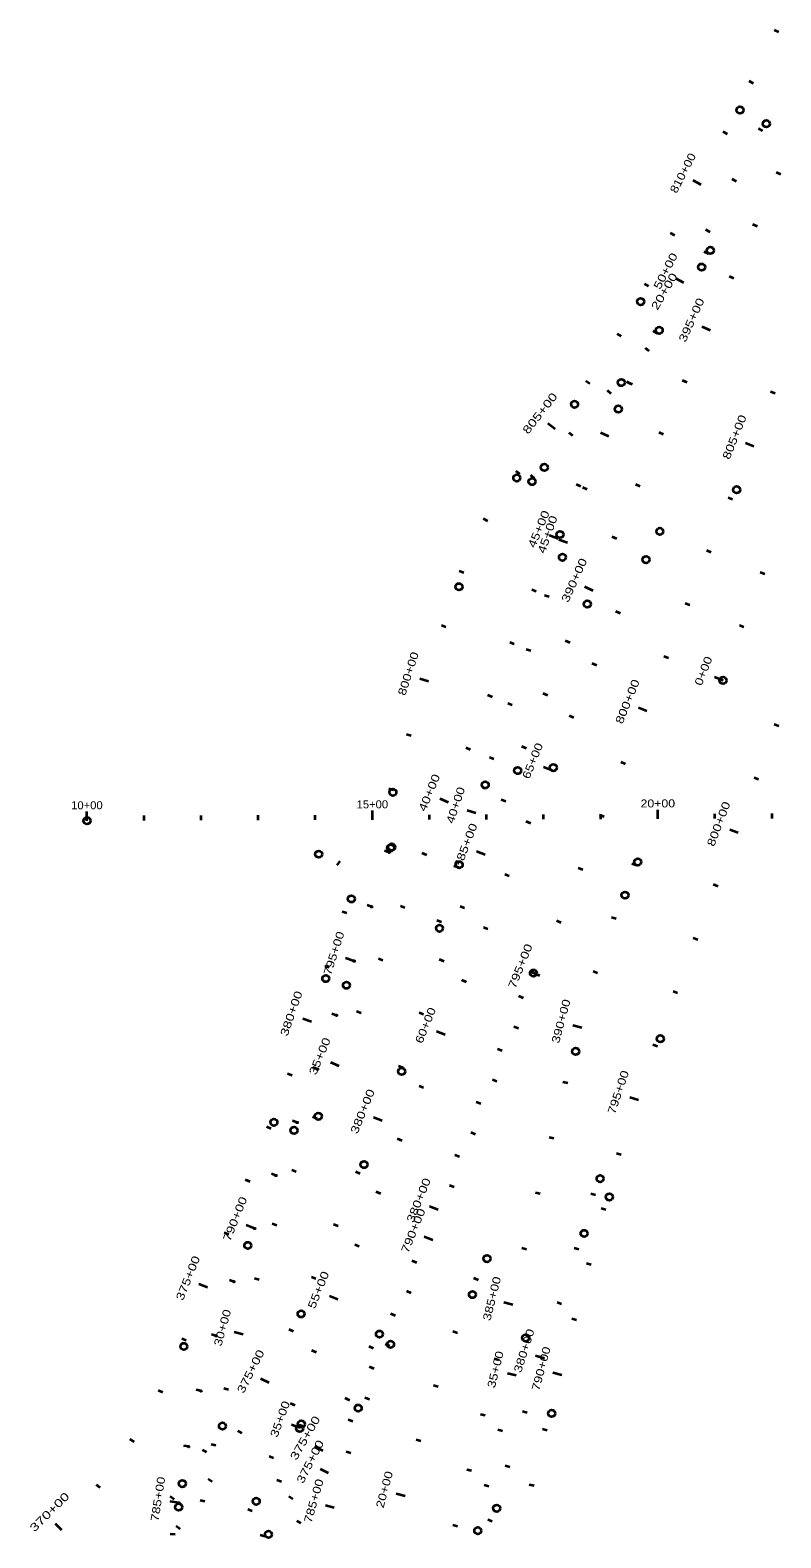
# Model space of a CAD drawing. Extents: x 2357892 to 2370172, y 6966790 to 6985499.
# Drawn here: x 2364077 to 2365392, y 6979263 to 6981905 of the extents above; entities that cross this region are included whole.
import ezdxf
from ezdxf.enums import TextEntityAlignment as Align

# ---------------------------------------------------------------- set-up
doc = ezdxf.new("R2010")
doc.units = 0
doc.header["$LTSCALE"] = 5.6
doc.header["$PDMODE"] = 32
doc.header["$PDSIZE"] = 2.8
doc.layers.add('28', color=7, linetype='Continuous', lineweight=35)
doc.layers.add('7', color=7, linetype='Continuous')

msp = doc.modelspace()

# ---------------------------------------------------------------- linework, layer by layer
at = {"layer": '28'}
for p, q in [((2365389.008, 6981900.982), (2365381.359, 6981904.69)), ((2365344.597, 6981811.386), (2365337.015, 6981815.228)), ((2365298.789, 6981722.496), (2365291.243, 6981726.408)), ((2365360.417, 6981728.387), (2365352.87, 6981732.299)), ((2365314.393, 6981639.607), (2365306.847, 6981643.519)), ((2365392.261, 6981651.987), (2365384.511, 6981655.478)), ((2365252.765, 6981633.716), (2365238.561, 6981641.08)), ((2365351.188, 6981560.811), (2365343.438, 6981564.303)), ((2365206.742, 6981544.936), (2365199.196, 6981548.848)), ((2365268.37, 6981550.827), (2365260.823, 6981554.739)), ((2365265.495, 6981512.687), (2365257.949, 6981516.599)), ((2365160.718, 6981456.157), (2365153.172, 6981460.069)), ((2365222.346, 6981462.048), (2365208.141, 6981469.412)), ((2365310.115, 6981469.636), (2365302.365, 6981473.127)), ((2365269.041, 6981378.46), (2365254.453, 6981385.032)), ((2365112.839, 6981368.387), (2365105.544, 6981372.75)), ((2365176.323, 6981373.268), (2365168.776, 6981377.18)), ((2365176.442, 6981373.485), (2365168.888, 6981377.381)), ((2365161.686, 6981342.301), (2365155.111, 6981347.688)), ((2365057.834, 6981284.912), (2365050.947, 6981289.894)), ((2365095.086, 6981267.72), (2365088.792, 6981273.433)), ((2365130.299, 6981284.488), (2365122.753, 6981288.4)), ((2365132.166, 6981283.827), (2365124.48, 6981287.457)), ((2365227.968, 6981287.285), (2365220.218, 6981290.776)), ((2365382.217, 6981268.052), (2365374.313, 6981271.179)), ((2364996.799, 6981205.708), (2364984.211, 6981215.585)), ((2365027.876, 6981193.674), (2365021.582, 6981199.386)), ((2365084.677, 6981195.503), (2365077.063, 6981199.281)), ((2365091.046, 6981192.678), (2365083.238, 6981196.038)), ((2365186.895, 6981196.109), (2365179.145, 6981199.6)), ((2365345.225, 6981175.145), (2365330.373, 6981181.096)), ((2364935.071, 6981127.034), (2364928.383, 6981132.281)), ((2364961.019, 6981119.316), (2364954.501, 6981124.772)), ((2365041.808, 6981105.164), (2365034.066, 6981108.673)), ((2365053.132, 6981100.15), (2365045.212, 6981103.235)), ((2365145.822, 6981104.933), (2365138.072, 6981108.425)), ((2365307.836, 6981082.398), (2365299.957, 6981085.588)), ((2364878.897, 6981044.431), (2364871.505, 6981048.627)), ((2365002.107, 6981013.388), (2364987.33, 6981019.525)), ((2365018.471, 6981006.354), (2365003.368, 6981011.638)), ((2365104.749, 6981013.758), (2365096.999, 6981017.249)), ((2365270.312, 6980989.705), (2365262.433, 6980992.895)), ((2364836.832, 6980953.831), (2364828.857, 6980956.77)), ((2365364.213, 6980951.683), (2365356.304, 6980954.795)), ((2364963.752, 6980921.036), (2364955.903, 6980924.296)), ((2364986.213, 6980911.7), (2364978.164, 6980914.432)), ((2365063.676, 6980922.582), (2365049.088, 6980929.154)), ((2365111.158, 6980882.854), (2365103.454, 6980886.445)), ((2365232.789, 6980897.013), (2365224.91, 6980900.202)), ((2364805.714, 6980858.802), (2364797.622, 6980861.404)), ((2365327.595, 6980858.628), (2365319.685, 6980861.741)), ((2364925.398, 6980828.683), (2364917.548, 6980831.943)), ((2365023.045, 6980831.21), (2365015.25, 6980834.6)), ((2364954.073, 6980817.006), (2364946.024, 6980819.738)), ((2365195.265, 6980804.32), (2365187.386, 6980807.509)), ((2365069.714, 6980791.848), (2365061.948, 6980795.304)), ((2365290.976, 6980765.574), (2365276.087, 6980771.433)), ((2364775.111, 6980763.6), (2364759.879, 6980768.497)), ((2364887.044, 6980736.331), (2364879.194, 6980739.591)), ((2364921.933, 6980722.312), (2364913.884, 6980725.043)), ((2364983.962, 6980739.164), (2364976.11, 6980742.418)), ((2365029.864, 6980700.133), (2365022.039, 6980703.452)), ((2365157.741, 6980711.627), (2365142.91, 6980717.631)), ((2364744.508, 6980668.398), (2364736.416, 6980670.999)), ((2365388.666, 6980685.166), (2365380.718, 6980688.178)), ((2364848.69, 6980643.979), (2364840.84, 6980647.239)), ((2364946.492, 6980646.451), (2364938.584, 6980649.567)), ((2364889.793, 6980627.617), (2364881.744, 6980630.349)), ((2364991.618, 6980607.737), (2364976.787, 6980613.741)), ((2365120.218, 6980618.934), (2365112.339, 6980622.123)), ((2365353.222, 6980591.658), (2365345.274, 6980594.671)), ((2364713.904, 6980573.196), (2364705.812, 6980575.797)), ((2364176.827, 6980519.731), (2364176.775, 6980535.731)), ((2364676.824, 6980521.354), (2364676.772, 6980537.354)), ((2364810.336, 6980551.626), (2364795.559, 6980557.763)), ((2364857.879, 6980532.847), (2364842.682, 6980537.851)), ((2364910.369, 6980553.204), (2364902.438, 6980556.262)), ((2365176.822, 6980522.976), (2365176.77, 6980538.976)), ((2364276.826, 6980520.056), (2364276.799, 6980528.555)), ((2364376.826, 6980520.38), (2364376.798, 6980528.88)), ((2364476.825, 6980520.705), (2364476.798, 6980529.205)), ((2364576.825, 6980521.029), (2364576.797, 6980529.529)), ((2364776.824, 6980521.678), (2364776.796, 6980530.178)), ((2364876.823, 6980522.003), (2364876.796, 6980530.503)), ((2364954.095, 6980515.044), (2364946.216, 6980518.233)), ((2364976.823, 6980522.327), (2364976.795, 6980530.827)), ((2365082.694, 6980526.241), (2365074.815, 6980529.43)), ((2365076.822, 6980522.652), (2365076.795, 6980531.152)), ((2365276.821, 6980523.301), (2365276.794, 6980531.801)), ((2365376.821, 6980523.625), (2365376.793, 6980532.125)), ((2365317.777, 6980498.15), (2365302.816, 6980503.822)), ((2364706.145, 6980464.107), (2364698.053, 6980466.708)), ((2364771.981, 6980459.274), (2364764.131, 6980462.534)), ((2364874.387, 6980459.902), (2364859.459, 6980465.659)), ((2364619.564, 6980448.565), (2364614.374, 6980441.834)), ((2364827.433, 6980437.596), (2364819.317, 6980440.12)), ((2365045.17, 6980433.548), (2365037.291, 6980436.738)), ((2365139.193, 6980440.927), (2365131.264, 6980443.99)), ((2364916.572, 6980422.35), (2364908.694, 6980425.54)), ((2365282.332, 6980404.643), (2365274.384, 6980407.656)), ((2364631.939, 6980357.46), (2364623.847, 6980360.062)), ((2364675.535, 6980368.907), (2364667.443, 6980371.508)), ((2364733.627, 6980366.922), (2364725.777, 6980370.182)), ((2364838.405, 6980366.599), (2364830.475, 6980369.658)), ((2365103.563, 6980347.492), (2365095.576, 6980350.4)), ((2364797.737, 6980342.107), (2364789.62, 6980344.631)), ((2364879.05, 6980329.657), (2364871.171, 6980332.847)), ((2365007.647, 6980340.855), (2364999.768, 6980344.045)), ((2365246.888, 6980311.135), (2365238.939, 6980314.148)), ((2364644.925, 6980273.706), (2364629.693, 6980278.604)), ((2364695.273, 6980274.569), (2364687.423, 6980277.829)), ((2364802.423, 6980273.297), (2364794.493, 6980276.356)), ((2364601.329, 6980262.26), (2364593.237, 6980264.862)), ((2364970.123, 6980248.162), (2364955.292, 6980254.166)), ((2365071.409, 6980252.811), (2365063.303, 6980255.368)), ((2364841.527, 6980236.964), (2364833.648, 6980240.153)), ((2365211.443, 6980217.628), (2365203.495, 6980220.64)), ((2364941.375, 6980208.991), (2364933.49, 6980212.167)), ((2364569.918, 6980167.324), (2364554.792, 6980172.542)), ((2364613.93, 6980178.632), (2364605.877, 6980181.352)), ((2364656.919, 6980182.217), (2364649.069, 6980185.477)), ((2364766.442, 6980179.995), (2364758.511, 6980183.053)), ((2364804.004, 6980144.271), (2364789.173, 6980150.274)), ((2364932.599, 6980155.469), (2364924.72, 6980158.659)), ((2365043.416, 6980156.817), (2365027.962, 6980160.96)), ((2364904.015, 6980116.232), (2364896.13, 6980119.408)), ((2365176.033, 6980124.107), (2365168.07, 6980127.079)), ((2364580.701, 6980084.318), (2364572.721, 6980087.247)), ((2364618.564, 6980089.865), (2364603.788, 6980096.001)), ((2364730.46, 6980086.693), (2364722.529, 6980089.751)), ((2364536.058, 6980073.234), (2364528.098, 6980076.217)), ((2364895.076, 6980062.776), (2364887.197, 6980065.966)), ((2365018.938, 6980059.861), (2365010.688, 6980061.909)), ((2364766.481, 6980051.577), (2364758.603, 6980054.767)), ((2365142.707, 6980029.829), (2365127.531, 6980034.897)), ((2364866.655, 6980023.473), (2364858.77, 6980026.649)), ((2364499.74, 6979980.065), (2364491.852, 6979983.232)), ((2364545.013, 6979990.906), (2364537.114, 6979994.043)), ((2364580.213, 6979997.511), (2364572.359, 6980000.76)), ((2364693.769, 6979993.668), (2364678.936, 6979999.668)), ((2364728.959, 6979958.884), (2364721.08, 6979962.073)), ((2364857.552, 6979970.083), (2364849.673, 6979973.273)), ((2364994.843, 6979962.807), (2364986.594, 6979964.855)), ((2364829.295, 6979930.714), (2364821.41, 6979933.89)), ((2365112.691, 6979934.445), (2365104.54, 6979936.855)), ((2364507.773, 6979898.099), (2364499.885, 6979901.266)), ((2364543.409, 6979904.534), (2364535.459, 6979907.542)), ((2364655.488, 6979901.287), (2364647.655, 6979904.587)), ((2364462.473, 6979887.268), (2364454.585, 6979890.436)), ((2364820.028, 6979877.391), (2364812.149, 6979880.58)), ((2364691.436, 6979866.191), (2364683.557, 6979869.38)), ((2364970.749, 6979865.753), (2364962.499, 6979867.801)), ((2365067.79, 6979863.827), (2365059.611, 6979866.138)), ((2364791.935, 6979837.955), (2364777.093, 6979843.933)), ((2365085.932, 6979838.096), (2365077.719, 6979840.286)), ((2364425.206, 6979794.472), (2364417.318, 6979797.64)), ((2364470.506, 6979805.302), (2364455.658, 6979811.265)), ((2364509.461, 6979810.477), (2364501.423, 6979813.24)), ((2364616.657, 6979809.134), (2364608.824, 6979812.435)), ((2364653.913, 6979773.498), (2364646.034, 6979776.687)), ((2364782.505, 6979784.698), (2364767.674, 6979790.701)), ((2364946.654, 6979768.699), (2364938.405, 6979770.747)), ((2365038.639, 6979768.176), (2365030.539, 6979770.752)), ((2364754.575, 6979745.196), (2364746.69, 6979748.372)), ((2365060.164, 6979741.473), (2365051.951, 6979743.663)), ((2364434.363, 6979712.07), (2364426.368, 6979714.955)), ((2364478.402, 6979715.427), (2364470.283, 6979717.943)), ((2364577.825, 6979716.981), (2364569.992, 6979720.282)), ((2364862.403, 6979714.9), (2364854.524, 6979718.089)), ((2364387.939, 6979701.676), (2364373.091, 6979707.638)), ((2364744.981, 6979692.005), (2364737.102, 6979695.194)), ((2364616.39, 6979680.804), (2364601.559, 6979686.808)), ((2364922.56, 6979671.645), (2364907.031, 6979675.5)), ((2365008.332, 6979672.879), (2365000.232, 6979675.456)), ((2364717.215, 6979652.437), (2364709.33, 6979655.613)), ((2365034.396, 6979644.85), (2365026.183, 6979647.04)), ((2364350.671, 6979608.879), (2364342.784, 6979612.047)), ((2364402.895, 6979617.162), (2364394.759, 6979619.625)), ((2364450.259, 6979619.473), (2364434.839, 6979623.741)), ((2364538.723, 6979624.945), (2364530.949, 6979628.382)), ((2364825.697, 6979621.884), (2364817.743, 6979624.882)), ((2364578.868, 6979588.111), (2364570.989, 6979591.3)), ((2364678.727, 6979594.965), (2364670.897, 6979598.271)), ((2364707.459, 6979599.311), (2364699.577, 6979602.492)), ((2364679.855, 6979559.678), (2364671.971, 6979562.854)), ((2364898.465, 6979574.591), (2364890.216, 6979576.639)), ((2364978.025, 6979577.583), (2364962.778, 6979582.432)), ((2364495.904, 6979534.588), (2364481.63, 6979541.816)), ((2364791.994, 6979527.739), (2364783.944, 6979530.471)), ((2364928.823, 6979547.464), (2364913.295, 6979551.319)), ((2365008.628, 6979548.227), (2364993.169, 6979552.35)), ((2364309.617, 6979517.742), (2364302.058, 6979521.629)), ((2364376.436, 6979520.738), (2364368.183, 6979522.772)), ((2364425.061, 6979522.704), (2364416.803, 6979524.72)), ((2364637.035, 6979504.088), (2364629.421, 6979507.866)), ((2364671.662, 6979505.943), (2364663.674, 6979508.847)), ((2364541.345, 6979495.418), (2364533.466, 6979498.607)), ((2364874.371, 6979477.538), (2364866.121, 6979479.586)), ((2364947.718, 6979482.286), (2364939.618, 6979484.862)), ((2364448.415, 6979446.597), (2364441.043, 6979450.828)), ((2364549.888, 6979456.092), (2364534.841, 6979461.533)), ((2364642.286, 6979467.005), (2364634.459, 6979470.32)), ((2364904.729, 6979450.41), (2364896.479, 6979452.458)), ((2364983.02, 6979451.562), (2364974.784, 6979453.664)), ((2364259.318, 6979431.366), (2364252.206, 6979436.022)), ((2364355.06, 6979423.061), (2364346.712, 6979424.66)), ((2364402.829, 6979425.21), (2364394.513, 6979426.973)), ((2364761.447, 6979432.524), (2364753.311, 6979434.985)), ((2364386.257, 6979413.157), (2364379.075, 6979417.703)), ((2364503.822, 6979402.724), (2364495.943, 6979405.914)), ((2364589.872, 6979415.925), (2364576.001, 6979423.9)), ((2364639.146, 6979411.383), (2364631.061, 6979414.006)), ((2364600.103, 6979376.36), (2364585.841, 6979383.613)), ((2364850.276, 6979380.484), (2364842.026, 6979382.532)), ((2364917.411, 6979386.989), (2364909.311, 6979389.565)), ((2364200.266, 6979350.72), (2364193.68, 6979356.094)), ((2364396.386, 6979361.211), (2364389.245, 6979365.823)), ((2364517.489, 6979361.491), (2364509.401, 6979364.104)), ((2364880.634, 6979353.356), (2364872.385, 6979355.404)), ((2364959.986, 6979354.256), (2364951.682, 6979356.069)), ((2364338.522, 6979324.445), (2364322.714, 6979326.912)), ((2364329.692, 6979330.721), (2364322.866, 6979335.787)), ((2364383.584, 6979327.083), (2364375.219, 6979328.592)), ((2364537.415, 6979330.807), (2364530.318, 6979335.485)), ((2364609.95, 6979315.745), (2364594.568, 6979320.149)), ((2364734.09, 6979336.344), (2364718.63, 6979340.464)), ((2364466.434, 6979309.977), (2364458.507, 6979313.044)), ((2364551.7, 6979288.878), (2364544.41, 6979293.25)), ((2364886.741, 6979291.813), (2364878.742, 6979294.687)), ((2364133.107, 6979276.689), (2364121.836, 6979288.045)), ((2364331.203, 6979268.941), (2364322.763, 6979269.95)), ((2364339.959, 6979278.666), (2364333.07, 6979283.645)), ((2364488.411, 6979265.817), (2364480.237, 6979268.147)), ((2364826.181, 6979283.43), (2364817.932, 6979285.478))]:
    msp.add_line(p, q, dxfattribs=at)
for centre in [(2365320.703, 6981764.768), (2365366.872, 6981740.84), (2365268.726, 6981518.92), (2365253.485, 6981489.521), (2365146.725, 6981429.163), (2365179.213, 6981378.844), (2365112.846, 6981287.286), (2365030.922, 6981249.199), (2365107.667, 6981240.83), (2364977.996, 6981138.719), (2364929.74, 6981120.24), (2364956.546, 6981113.907), (2365314.805, 6981099.614), (2365005.316, 6981021.116), (2365180.29, 6981026.581), (2365009.771, 6980981.11), (2365156.125, 6980977.1), (2364828.422, 6980929.443), (2365053.192, 6980899.31), (2365290.976, 6980765.574), (2364931.348, 6980607.602), (2364993.637, 6980612.723), (2364874.462, 6980582.446), (2364712.707, 6980569.471), (2364176.827, 6980519.731), (2364582.732, 6980461.048), (2364708.707, 6980472.076), (2364710.605, 6980473.464), (2364828.941, 6980442.444), (2365141.704, 6980447.427), (2364640.049, 6980382.682), (2365119.23, 6980389.252), (2364794.365, 6980331.264), (2364595.173, 6980243.114), (2364958.97, 6980252.678), (2364631.349, 6980231.481), (2365181.167, 6980137.755), (2365032.768, 6980115.569), (2364728.086, 6980080.537), (2364582.017, 6980001.863), (2364504.275, 6979991.359), (2364539.534, 6979977.185), (2364662.224, 6979917.272), (2365075.714, 6979892.584), (2365091.914, 6979860.529), (2365047.675, 6979796.588), (2364458.537, 6979775.499), (2364877.608, 6979752.459), (2364852.132, 6979689.528), (2364552.018, 6979655.737), (2364689.151, 6979620.236), (2364945.21, 6979613.471), (2364346.527, 6979598.56), (2364708.63, 6979602.209), (2364652.001, 6979490.521), (2364990.778, 6979481.291), (2364414.155, 6979459.247), (2364549.473, 6979454.944), (2364552.292, 6979462.741), (2364343.8, 6979358.262), (2364337.397, 6979317.233), (2364473.326, 6979327.388), (2364894.547, 6979315.093), (2364494.819, 6979269.3), (2364861.391, 6979275.844)]:
    msp.add_circle(centre, 6, dxfattribs=at)
at = {"layer": '7'}
for p in [(2364706.145, 6980464.107), (2364675.535, 6980368.907), (2364644.925, 6980273.706), (2364613.93, 6980178.632), (2364580.701, 6980084.318), (2364545.013, 6979990.906), (2364507.773, 6979898.099), (2364470.506, 6979805.302), (2364434.363, 6979712.07), (2364402.895, 6979617.162), (2364376.436, 6979520.738), (2364355.06, 6979423.061), (2364338.522, 6979324.445)]:
    msp.add_point(p, dxfattribs=at)

# ---------------------------------------------------------------- texts
at = {"layer": '28'}
for s, rotation, width, p in [('810+00', 62.598, 1.2, (2365226.914, 6981651.205)), ('50+00', 62.598, 1.3, (2365196.495, 6981479.537)), ('20+00', 59.671, 1.35, (2365194.051, 6981443.492)), ('395+00', 65.749, 1.3, (2365242.073, 6981394.069)), ('805+00', 51.882, 1.35, (2364975.801, 6981229.165)), ('805+00', 68.165, 1.3, (2365317.493, 6981189.28)), ('45+00', 67.447, 1.3, (2364974.593, 6981027.963)), ('45+00', 70.718, 1.3, (2364990.018, 6981018.903)), ('390+00', 65.749, 1.3, (2365036.707, 6980938.19)), ('800+00', 72.18, 1.25, (2364746.288, 6980775.23)), ('0+00', 68.519, 1.25, (2365263.138, 6980779.489)), ('800+00', 67.961, 1.3, (2365130.07, 6980725.886)), ('65+00', 67.962, 1.25, (2364963.947, 6980621.996)), ('40+00', 67.447, 1.3, (2364782.822, 6980566.201)), ('40+00', 71.775, 1.25, (2364829.156, 6980544.731)), ('10+00', 0.186, 1.05, (2364176.785, 6980539.731)), ('15+00', 0.186, 1.05, (2364676.783, 6980541.354)), ('20+00', 0.186, 1.15, (2365176.78, 6980542.976)), ('800+00', 69.24, 1.3, (2365289.731, 6980511.619)), ('385+00', 68.911, 1.3, (2364846.435, 6980473.575)), ('795+00', 72.176, 1.25, (2364616.102, 6980285.338)), ('795+00', 67.961, 1.3, (2364942.451, 6980262.421)), ('380+00', 70.965, 1.3, (2364541.401, 6980179.718)), ('60+00', 67.962, 1.25, (2364776.333, 6980158.529)), ('390+00', 74.993, 1.25, (2365013.959, 6980166.656)), ('35+00', 67.447, 1.3, (2364591.05, 6980104.44)), ('795+00', 71.532, 1.25, (2365114.044, 6980041.866)), ('380+00', 67.977, 1.3, (2364666.093, 6980007.919)), ('380+00', 68.062, 1.3, (2364764.233, 6979852.153)), ('790+00', 68.12, 1.3, (2364442.786, 6979819.463)), ('790+00', 67.961, 1.3, (2364754.833, 6979798.956)), ('375+00', 68.12, 1.3, (2364360.219, 6979715.838)), ('55+00', 67.962, 1.3, (2364588.719, 6979695.063)), ('385+00', 76.058, 1.25, (2364892.891, 6979680.801)), ('30+00', 74.529, 1.25, (2364420.9, 6979629.61)), ('380+00', 72.358, 1.25, (2364949.158, 6979589.1)), ('375+00', 63.144, 1.3, (2364469.848, 6979551.755)), ('35+00', 76.058, 1.25, (2364899.156, 6979556.62)), ('790+00', 75.068, 1.25, (2364979.156, 6979558.018)), ('35+00', 70.119, 1.25, (2364521.596, 6979469.014)), ('375+00', 60.105, 1.35, (2364565.003, 6979434.865)), ('375+00', 63.044, 1.3, (2364574.084, 6979393.585)), ('20+00', 75.078, 1.25, (2364704.617, 6979346.129)), ('785+00', 81.129, 1.25, (2364308.062, 6979330.305)), ('785+00', 74.024, 1.25, (2364580.699, 6979326.204)), ('370+00', 44.787, 1.4, (2364116.2, 6979303.586))]:
    msp.add_text(s, height=14, rotation=rotation, dxfattribs=dict(at, width=width)).set_placement(p, align=Align.CENTER)

doc.saveas('drawing.dxf')
